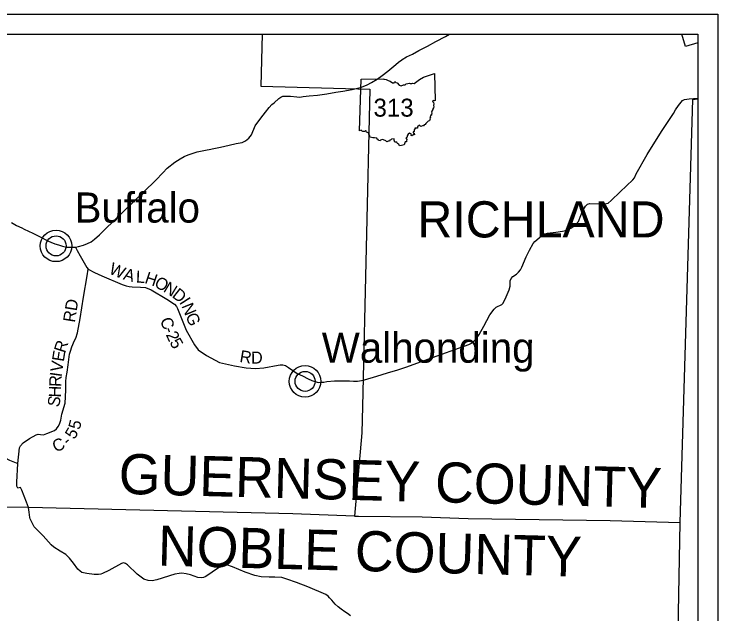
# Model space of a CAD drawing. Extents: x -452339 to 6403467, y -1 to 1814750.
# Drawn here: x -50370 to -32848, y 1640875 to 1655812 of the extents above; entities that cross this region are included whole.
import ezdxf

# ---------------------------------------------------------------- set-up
doc = ezdxf.new("R2010")
doc.units = 0
for name, color, linetype in [('Default', 7, 'Continuous'), ('GM_X_Adjacent_County_Text', 7, 'Continuous'), ('GM_X_County', 7, 'Continuous'), ('GM_X_County_Road', 7, 'Continuous'), ('GM_X_County_Road_Text', 7, 'Continuous'), ('GM_X_Minor_River_Text', 7, 'Continuous'), ('GM_X_Section_Text', 7, 'Continuous'), ('GM_X_Township_Subdivision_Text', 7, 'Continuous')]:
    doc.layers.add(name, color=color, linetype=linetype)

msp = doc.modelspace()

# ---------------------------------------------------------------- linework, layer by layer
at = {"layer": 'Default'}
for p, q in [((-90726, 1655312), (-33348, 1655312)), ((-33348, 1655312), (-33348, 1597935)), ((-41770, 1652904), (-41728, 1654195))]:
    msp.add_line(p, q, dxfattribs=at)
msp.add_lwpolyline([(-91226, 1655812), (-32848, 1655812), (-32848, 1597435), (-91226, 1597435)], close=True, dxfattribs=at)
for points in [[(-41728, 1654195), (-41156, 1654203), (-41165, 1654188), (-41111, 1654185), (-41053, 1654157), (-41005, 1654140), (-40946, 1654099), (-40910, 1654099), (-40895, 1654133), (-40868, 1654107), (-40836, 1654102), (-40780, 1654040), (-40734, 1654027), (-40678, 1654048), (-40637, 1654052), (-40607, 1654073), (-40529, 1654090), (-40506, 1654080), (-40465, 1654082), (-40444, 1654090), (-40408, 1654083), (-40344, 1654130), (-40278, 1654185), (-40177, 1654237), (-40026, 1654287), (-39907, 1654331), (-39889, 1653661)], [(-40721, 1646984), (-40589, 1647025), (-40070, 1647221), (-39048, 1647581), (-38964, 1647629), (-38863, 1647726), (-38794, 1647833), (-38676, 1648044), (-38525, 1648321), (-38420, 1648466), (-38368, 1648510), (-38225, 1648578), (-38193, 1648616), (-38117, 1648772), (-38046, 1648945), (-38021, 1649033), (-38024, 1649125), (-38020, 1649169), (-37995, 1649229), (-37951, 1649274), (-37866, 1649338), (-37814, 1649383), (-37767, 1649443), (-37732, 1649509), (-37618, 1649764), (-37540, 1649935), (-37447, 1650102), (-37405, 1650148), (-37239, 1650289), (-37179, 1650326), (-37087, 1650355), (-36883, 1650381), (-36718, 1650408), (-36640, 1650423), (-36508, 1650484), (-36397, 1650563), (-36318, 1650650), (-36259, 1650793), (-36212, 1650919), (-36168, 1650988), (-36141, 1651031), (-36096, 1651076), (-36040, 1651094), (-35667, 1651086), (-35584, 1651107), (-35504, 1651172), (-35278, 1651387), (-34969, 1651688), (-34929, 1651738), (-34882, 1651835), (-34607, 1652313), (-34252, 1652885), (-33958, 1653333), (-33902, 1653425), (-33828, 1653532), (-33763, 1653620), (-33727, 1653656), (-33678, 1653683), (-33562, 1653698), (-33348, 1653714)], [(-39889, 1653661), (-39907, 1653652), (-39934, 1653656), (-39953, 1653637), (-39930, 1653606), (-39919, 1653573), (-39929, 1653536), (-39919, 1653506), (-39926, 1653481), (-39943, 1653456), (-39949, 1653432), (-39964, 1653407), (-39963, 1653393), (-39976, 1653382), (-39974, 1653340), (-39981, 1653316), (-39978, 1653296), (-40001, 1653291), (-39996, 1653275), (-40010, 1653262), (-40007, 1653240), (-40024, 1653226), (-40008, 1653198), (-40021, 1653189), (-40031, 1653154), (-40060, 1653147), (-40118, 1653085), (-40139, 1653061), (-40162, 1653056), (-40175, 1653031), (-40203, 1653031), (-40246, 1653014), (-40274, 1653043), (-40323, 1653008), (-40328, 1652968), (-40390, 1652969), (-40387, 1652949), (-40401, 1652943), (-40414, 1652923), (-40406, 1652886), (-40435, 1652877), (-40432, 1652856), (-40413, 1652844), (-40405, 1652803), (-40436, 1652811), (-40461, 1652777), (-40487, 1652785), (-40478, 1652814), (-40522, 1652849), (-40563, 1652821), (-40585, 1652777), (-40585, 1652747), (-40616, 1652729), (-40596, 1652687), (-40600, 1652658), (-40599, 1652631), (-40637, 1652632), (-40661, 1652558)], [(-40661, 1652558), (-40728, 1652543), (-40774, 1652535), (-40790, 1652569), (-40823, 1652586), (-40845, 1652620), (-40893, 1652625), (-40904, 1652671), (-40909, 1652709), (-40974, 1652700), (-40992, 1652677), (-41015, 1652671), (-41028, 1652647), (-41060, 1652645), (-41094, 1652634), (-41116, 1652657), (-41171, 1652680), (-41196, 1652692), (-41248, 1652674), (-41259, 1652652), (-41301, 1652661), (-41310, 1652686), (-41335, 1652693), (-41341, 1652719), (-41395, 1652732), (-41436, 1652727), (-41508, 1652748), (-41512, 1652781), (-41537, 1652823), (-41549, 1652851), (-41595, 1652873), (-41605, 1652907), (-41619, 1652906), (-41633, 1652892), (-41684, 1652886), (-41704, 1652900), (-41732, 1652924), (-41770, 1652904)], [(-48844, 1650011), (-48800, 1649922), (-48727, 1649789), (-48628, 1649615), (-48557, 1649501), (-48523, 1649456), (-48364, 1649377), (-48184, 1649298), (-47676, 1649081), (-47580, 1649043), (-47505, 1649026), (-47427, 1649019), (-47220, 1649013), (-47097, 1649000), (-46957, 1648946), (-46564, 1648713), (-46380, 1648589), (-46327, 1648533), (-46301, 1648484), (-46086, 1647944), (-45875, 1647573), (-45783, 1647455), (-45576, 1647312), (-45259, 1647139), (-44958, 1647071), (-44880, 1647056), (-44594, 1647001), (-44363, 1646987), (-44151, 1647002), (-43798, 1647068), (-43749, 1647077), (-43683, 1647079), (-43609, 1647060), (-43535, 1647015), (-43319, 1646862), (-43191, 1646803), (-43051, 1646732), (-42954, 1646689), (-42825, 1646646), (-42781, 1646642), (-42714, 1646648), (-42658, 1646648), (-42586, 1646663), (-42390, 1646677), (-42155, 1646679), (-42017, 1646676), (-41916, 1646668), (-41818, 1646674), (-41720, 1646686), (-41678, 1646698), (-41648, 1646706)], [(-50014, 1643522), (-50058, 1643662), (-50176, 1643953), (-50212, 1644024), (-50279, 1644009), (-50300, 1644056), (-50303, 1644156), (-50280, 1644617), (-50231, 1645011), (-50213, 1645059), (-50146, 1645136), (-49987, 1645246), (-49821, 1645338), (-49771, 1645352), (-49715, 1645345), (-49637, 1645338), (-49553, 1645367), (-49367, 1645443), (-49313, 1645484), (-49270, 1645540), (-49240, 1645597), (-49206, 1645701), (-49179, 1645849), (-49100, 1646124), (-49083, 1646449), (-49083, 1646659), (-49075, 1646764), (-49045, 1646895), (-49024, 1647080), (-48986, 1647341), (-48969, 1647421), (-48931, 1647523), (-48864, 1647683), (-48830, 1647746), (-48788, 1647876), (-48721, 1648234), (-48644, 1648766), (-48553, 1649298), (-48523, 1649456)], [(-41648, 1646706), (-41340, 1646795), (-41070, 1646879), (-40819, 1646953), (-40721, 1646984)], [(-51696, 1645210), (-51443, 1645039), (-51381, 1645003), (-51286, 1644977), (-51184, 1644968), (-51055, 1644957), (-50946, 1644931), (-50813, 1644876), (-50484, 1644704), (-50280, 1644617)], [(-41991, 1640827), (-42069, 1640888), (-42134, 1640929), (-42231, 1640998), (-42299, 1641049), (-42376, 1641118), (-42461, 1641214), (-42518, 1641280), (-42554, 1641317), (-42613, 1641358), (-43061, 1641550), (-43342, 1641658), (-43583, 1641743), (-43707, 1641779), (-43875, 1641793), (-44019, 1641788), (-44221, 1641800), (-44378, 1641830), (-44615, 1641916), (-44931, 1642047), (-45070, 1642095), (-45132, 1642093), (-45210, 1642060), (-45282, 1642021), (-45437, 1641918), (-45596, 1641810), (-45652, 1641780), (-45700, 1641770), (-45794, 1641785), (-45981, 1641847), (-46086, 1641870), (-46196, 1641887), (-46264, 1641882), (-46366, 1641867), (-46812, 1641725), (-46934, 1641702), (-47030, 1641705), (-47136, 1641742), (-47308, 1641868), (-47549, 1642097), (-47595, 1642129), (-47621, 1642142), (-47648, 1642144), (-47697, 1642130), (-48014, 1641959), (-48170, 1641881), (-48206, 1641867), (-48264, 1641860), (-48380, 1641859), (-48559, 1641879), (-48679, 1641910), (-48726, 1641938), (-48780, 1641989), (-48890, 1642138), (-48989, 1642265), (-49028, 1642309), (-49082, 1642354), (-49220, 1642439), (-49379, 1642541), (-49448, 1642598), (-49513, 1642672), (-49646, 1642816), (-49867, 1643042), (-49967, 1643242), (-49976, 1643279), (-49982, 1643340), (-49994, 1643409), (-50014, 1643522)]]:
    msp.add_lwpolyline(points, dxfattribs=at)
at = {"layer": 'GM_X_County_Road'}
for points in [[(-45566, 1652429), (-45514, 1652439), (-45396, 1652462), (-45232, 1652498), (-45015, 1652547), (-44839, 1652588), (-44692, 1652613), (-44609, 1652654), (-44525, 1652720), (-44459, 1652802), (-44364, 1653026), (-44225, 1653220), (-44113, 1653367), (-44022, 1653483), (-43950, 1653559), (-43897, 1653602), (-43782, 1653707), (-43732, 1653744), (-43681, 1653767), (-43607, 1653770), (-43490, 1653764), (-43328, 1653749), (-43258, 1653746), (-43174, 1653757), (-43024, 1653774), (-42816, 1653795), (-42586, 1653823), (-42357, 1653866), (-42183, 1653890), (-41951, 1653935), (-41717, 1653996), (-41578, 1654052), (-41468, 1654108), (-41330, 1654195), (-41205, 1654281), (-41066, 1654393), (-40964, 1654477), (-40867, 1654559), (-40798, 1654616), (-40720, 1654669), (-40707, 1654678), (-40598, 1654744), (-40455, 1654817), (-40296, 1654904), (-40077, 1655017), (-39869, 1655131), (-39632, 1655253), (-39527, 1655312)], [(-49452, 1650132), (-49357, 1650093), (-49265, 1650063), (-49166, 1650036), (-49063, 1650009), (-48935, 1650009), (-48844, 1650011), (-48769, 1650022), (-48643, 1650054), (-48544, 1650097), (-48452, 1650144), (-48366, 1650204), (-48240, 1650311), (-48115, 1650442), (-47139, 1651382), (-46844, 1651680), (-46663, 1651861), (-46556, 1651973), (-46365, 1652126), (-46239, 1652208), (-46133, 1652263), (-46034, 1652306), (-45933, 1652339), (-45810, 1652378), (-45685, 1652407), (-45605, 1652422), (-45566, 1652429)], [(-50436, 1650620), (-50308, 1650550), (-50175, 1650486), (-50120, 1650459), (-49900, 1650353), (-49754, 1650282), (-49510, 1650156), (-49452, 1650132)]]:
    msp.add_lwpolyline(points, dxfattribs=at)
at = {"layer": 'GM_X_County_Road_Text'}
for centre, radius in [((-49325, 1650040), 393), ((-49325, 1650040), 249), ((-43125, 1646667), 393), ((-43125, 1646667), 249)]:
    msp.add_circle(centre, radius, dxfattribs=at)
at = {"layer": 'GM_X_Minor_River_Text'}
msp.add_lwpolyline([(-33348, 1655092), (-33653, 1655007), (-33745, 1655312)], dxfattribs=at)
at = {"layer": 'GM_X_Section_Text'}
for p, q in [((-44190, 1655312), (-44231, 1654016)), ((-44231, 1654016), (-41515, 1653940)), ((-41515, 1653940), (-41696, 1646042)), ((-33790, 1643152), (-33471, 1653688)), ((-33471, 1653688), (-33348, 1653704)), ((-41696, 1646042), (-41714, 1645385)), ((-41714, 1645385), (-41898, 1643312)), ((-50014, 1643522), (-52315, 1643569)), ((-43430, 1643367), (-50014, 1643522)), ((-41898, 1643312), (-43430, 1643367)), ((-41898, 1643312), (-41795, 1643310)), ((-41898, 1643312), (-41795, 1643310)), ((-41795, 1643310), (-40209, 1643290)), ((-40209, 1643290), (-39069, 1643248)), ((-40209, 1643290), (-39069, 1643248)), ((-39069, 1643248), (-35532, 1643200)), ((-39069, 1643248), (-35532, 1643200)), ((-35532, 1643200), (-33790, 1643152)), ((-35532, 1643200), (-33790, 1643152)), ((-34196, 1621943), (-33790, 1643152))]:
    msp.add_line(p, q, dxfattribs=at)

# ---------------------------------------------------------------- texts
at = {"layer": 'Default'}
msp.add_text('313', height=447.7, dxfattribs=at).set_placement((-41422, 1653258))
at = {"layer": 'GM_X_Adjacent_County_Text'}
for s, height, rotation, p in [('Buffalo', 750, 0, (-48864, 1650620)), ('Walhonding', 750, 0, (-42710, 1647130)), ('GUERNSEY COUNTY', 1000, 358.4869, (-47775, 1643867)), ('NOBLE COUNTY', 1000, 358.4869, (-46800, 1642078))]:
    msp.add_text(s, height=height, rotation=rotation, dxfattribs=at).set_placement(p)
at = {"layer": 'GM_X_County'}
for s, rotation, p in [('W', 336.5322, (-48030, 1649362)), ('A', 344.0822, (-47670, 1649209)), ('L', 357.6294, (-47340, 1649125)), ('H', 341.3185, (-47138, 1649119)), ('O', 330.1652, (-46902, 1649041)), ('N', 328.7101, (-46675, 1648911)), ('D', 321.9148, (-46457, 1648779)), ('I', 302.7613, (-46267, 1648636)), ('RD', 81.0031, (-48857, 1648120)), ('N', 292.2086, (-46207, 1648545)), ('C', 291.4274, (-46744, 1648193)), ('G', 292.3249, (-46107, 1648300)), ('2', 294.9234, (-46599, 1647831)), ('-', 292.4657, (-46652, 1647958)), ('5', 299.6253, (-46509, 1647639)), ('R', 72.1902, (-49100, 1647355)), ('E', 81.0886, (-49132, 1647145)), ('R', 350.6538, (-44768, 1647152)), ('D', 0.8434, (-44468, 1647107)), ('V', 81.4147, (-49172, 1646885)), ('I', 82.0278, (-49189, 1646764)), ('R', 87.6927, (-49198, 1646525)), ('H', 88.1853, (-49206, 1646262)), ('S', 78.3695, (-49254, 1646008)), ('5', 75.0386, (-48737, 1645446)), ('5', 58.959, (-48868, 1645204)), ('C', 23.1227, (-49339, 1644893)), ('-', 41.4708, (-49024, 1645045))]:
    msp.add_text(s, height=300, rotation=rotation, dxfattribs=at).set_placement(p)
at = {"layer": 'GM_X_Township_Subdivision_Text'}
msp.add_text('RICHLAND', height=900, rotation=0, dxfattribs=at).set_placement((-40329, 1650250))

doc.saveas('drawing.dxf')
